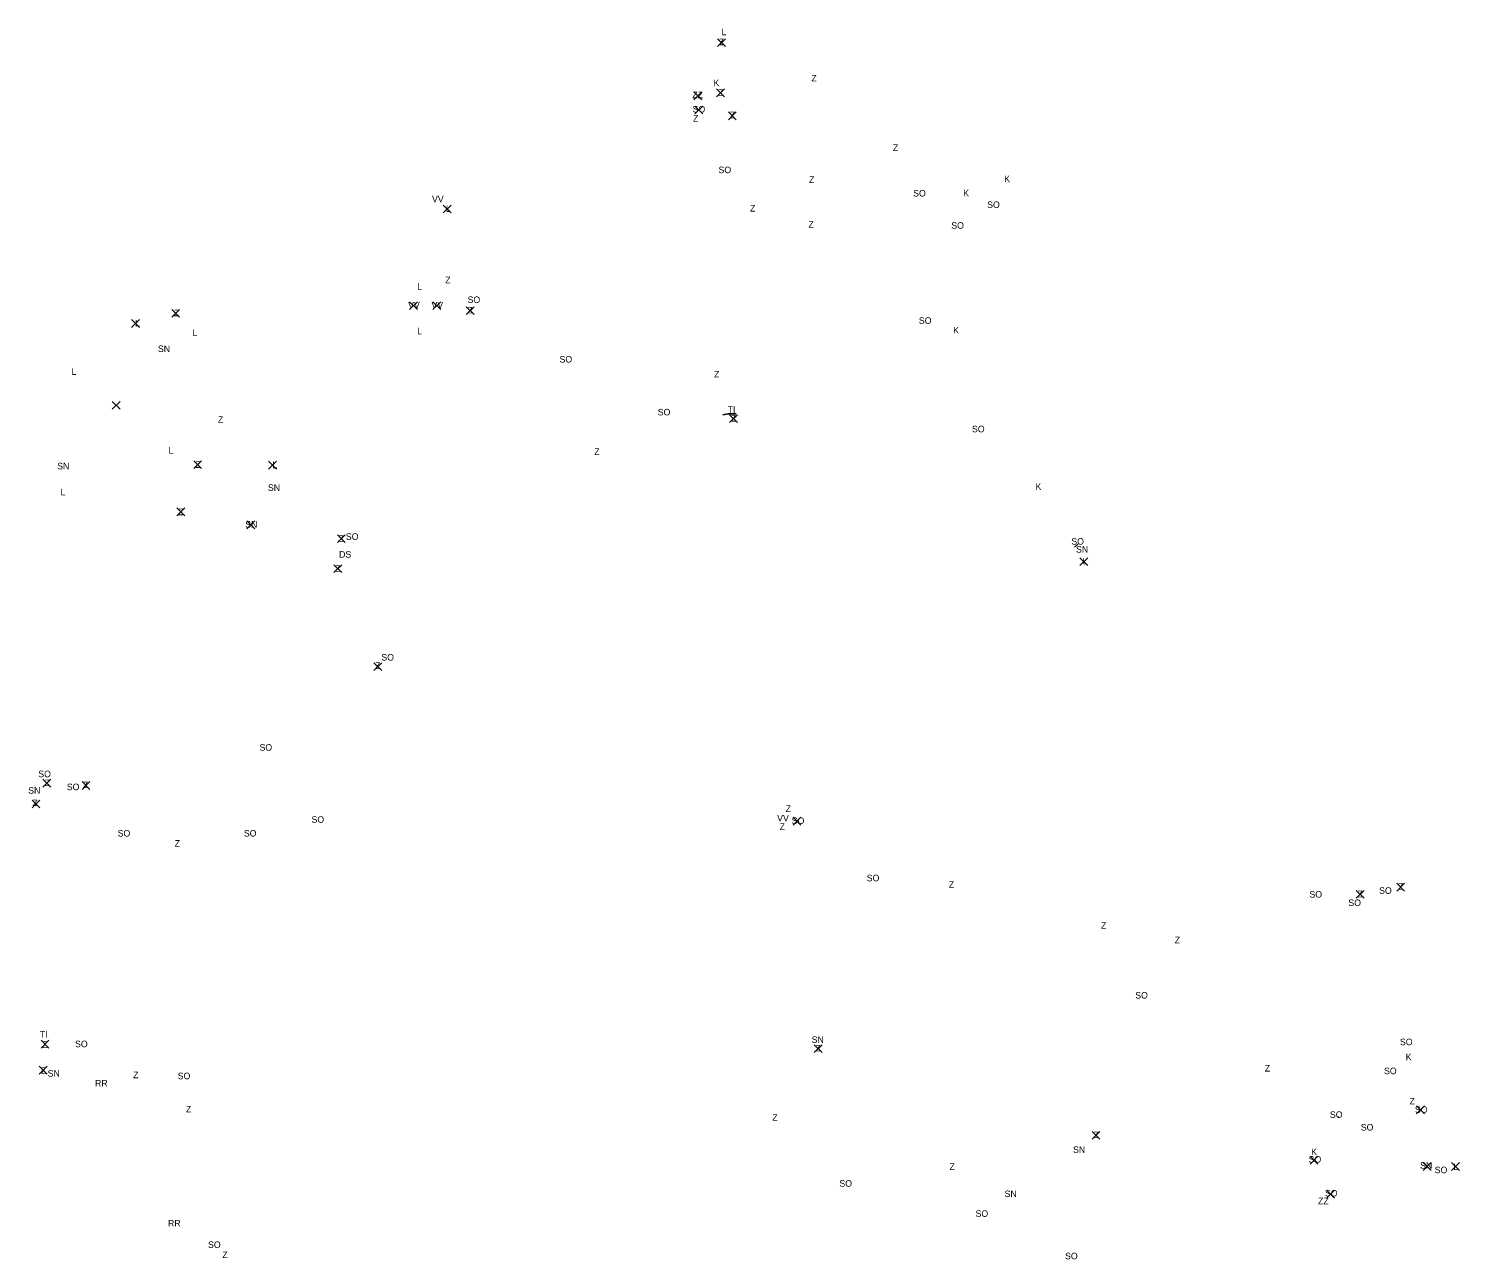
# Model space of a CAD drawing. Extents: x -444381 to -436234, y -1141793 to -1129925.
# Drawn here: x -442927 to -440739, y -1131807 to -1129925 of the extents above; entities that cross this region are included whole.
import ezdxf

# ---------------------------------------------------------------- set-up
doc = ezdxf.new("R2010")
doc.units = 0
for name, color, linetype in [('Implicitní', 7, 'Continuous'), ('Vrstva 200', 7, 'Continuous'), ('Vrstva 4', 7, 'Continuous')]:
    doc.layers.add(name, color=color, linetype=linetype)

msp = doc.modelspace()

# ---------------------------------------------------------------- linework, layer by layer
at = {"layer": 'Implicitní'}
msp.add_line((-440923.8, -1131589), (-440923.6, -1131589.3), dxfattribs=at)
at = {"layer": 'Vrstva 200'}
for p, q in [((-441873.3, -1129952.3), (-441861.3, -1129940.3)), ((-441873.3, -1129940.3), (-441861.3, -1129952.3)), ((-441909.4, -1130033.7), (-441897.4, -1130021.7)), ((-441909.4, -1130021.7), (-441897.4, -1130033.7)), ((-441874.8, -1130029), (-441862.8, -1130017)), ((-441874.8, -1130017), (-441862.8, -1130029)), ((-441908, -1130055.3), (-441896, -1130043.3)), ((-441908, -1130043.3), (-441896, -1130055.3)), ((-441856.7, -1130064.2), (-441844.7, -1130052.2)), ((-441856.7, -1130052.2), (-441844.7, -1130064.2)), ((-442292.6, -1130206.8), (-442280.6, -1130194.8)), ((-442292.6, -1130194.8), (-442280.6, -1130206.8)), ((-442344.1, -1130354.6), (-442332.1, -1130342.6)), ((-442344.1, -1130342.6), (-442332.1, -1130354.6)), ((-442308.3, -1130354.6), (-442296.3, -1130342.6)), ((-442308.3, -1130342.6), (-442296.3, -1130354.6)), ((-442257.5, -1130362.3), (-442245.5, -1130350.3)), ((-442257.5, -1130350.3), (-442245.5, -1130362.3)), ((-442769.1, -1130381.9), (-442757.1, -1130369.9)), ((-442769.1, -1130369.9), (-442757.1, -1130381.9)), ((-442707.8, -1130366.2), (-442695.8, -1130354.2)), ((-442707.8, -1130354.2), (-442695.8, -1130366.2)), ((-442798.6, -1130507), (-442786.6, -1130495)), ((-442798.6, -1130495), (-442786.6, -1130507)), ((-441854.8, -1130527.4), (-441842.8, -1130515.4)), ((-441854.8, -1130515.4), (-441842.8, -1130527.4)), ((-442674, -1130597.6), (-442662, -1130585.6)), ((-442674, -1130585.6), (-442662, -1130597.6)), ((-442559.6, -1130598.6), (-442547.6, -1130586.6)), ((-442559.6, -1130586.6), (-442547.6, -1130598.6)), ((-442699.9, -1130669.9), (-442687.9, -1130657.9)), ((-442699.9, -1130657.9), (-442687.9, -1130669.9)), ((-442592.8, -1130689.7), (-442580.8, -1130677.7)), ((-442592.8, -1130677.7), (-442580.8, -1130689.7)), ((-442454.4, -1130710.9), (-442442.4, -1130698.9)), ((-442454.4, -1130698.9), (-442442.4, -1130710.9)), ((-442459.7, -1130756.8), (-442447.7, -1130744.8)), ((-442459.7, -1130744.8), (-442447.7, -1130756.8)), ((-441319.3, -1130746.1), (-441307.3, -1130734.1)), ((-441319.3, -1130734.1), (-441307.3, -1130746.1)), ((-442398.5, -1130906.6), (-442386.5, -1130894.6)), ((-442398.5, -1130894.6), (-442386.5, -1130906.6)), ((-442904.8, -1131084.9), (-442892.8, -1131072.9)), ((-442904.8, -1131072.9), (-442892.8, -1131084.9)), ((-442844.8, -1131088.3), (-442832.8, -1131076.3)), ((-442844.8, -1131076.3), (-442832.8, -1131088.3)), ((-442921.2, -1131116.6), (-442909.2, -1131104.6)), ((-442921.2, -1131104.6), (-442909.2, -1131116.6)), ((-441757.7, -1131142.9), (-441745.7, -1131130.9)), ((-441757.7, -1131130.9), (-441745.7, -1131142.9)), ((-440896.8, -1131254.9), (-440884.8, -1131242.9)), ((-440896.8, -1131242.9), (-440884.8, -1131254.9)), ((-440834.8, -1131243.9), (-440822.8, -1131231.9)), ((-440834.8, -1131231.9), (-440822.8, -1131243.9)), ((-442907.4, -1131483.9), (-442895.4, -1131471.9)), ((-442907.4, -1131471.9), (-442895.4, -1131483.9)), ((-441725.5, -1131490.9), (-441713.5, -1131478.9)), ((-441725.5, -1131478.9), (-441713.5, -1131490.9)), ((-442910.4, -1131523.6), (-442898.4, -1131511.6)), ((-442910.4, -1131511.6), (-442898.4, -1131523.6)), ((-440804.7, -1131584.4), (-440792.7, -1131572.4)), ((-440804.7, -1131572.4), (-440792.7, -1131584.4)), ((-441300.7, -1131623.3), (-441288.7, -1131611.3)), ((-441300.7, -1131611.3), (-441288.7, -1131623.3)), ((-440967.4, -1131661.3), (-440955.4, -1131649.3)), ((-440967.4, -1131649.3), (-440955.4, -1131661.3)), ((-440794.5, -1131671), (-440782.5, -1131659)), ((-440794.5, -1131659), (-440782.5, -1131671)), ((-440751.1, -1131671), (-440739.1, -1131659)), ((-440751.1, -1131659), (-440739.1, -1131671)), ((-440942.1, -1131713.2), (-440930.1, -1131701.2)), ((-440942.1, -1131701.2), (-440930.1, -1131713.2))]:
    msp.add_line(p, q, dxfattribs=at)
at = {"layer": 'Vrstva 4'}
msp.add_line((-441322.7, -1130713.5), (-441327.7, -1130717.9), dxfattribs=at)
msp.add_lwpolyline([(-441844.6, -1130513.9), (-441856.9, -1130513.9), (-441865.4, -1130515.5)], dxfattribs=at)

# ---------------------------------------------------------------- texts
for s, p in [('L', (-441867.2, -1129934.9)), ('Z', (-441871.6, -1129950.2)), ('K', (-441879.5, -1130012.9)), ('Z', (-441729.9, -1130005.7)), ('ZZ', (-441911.9, -1130031.3)), ('Z', (-441872.5, -1130027.5)), ('SO', (-441911.4, -1130053.1)), ('Z', (-441910.8, -1130067.1)), ('Z', (-441854.7, -1130062)), ('Z', (-441605.2, -1130112)), ('SO', (-441871.8, -1130145.9)), ('Z', (-441733.5, -1130160.9)), ('K', (-441435, -1130159.7)), ('SO', (-441574.2, -1130181.6)), ('K', (-441497.7, -1130181.4)), ('VV', (-442309.8, -1130190.5)), ('L', (-442288.6, -1130205.1)), ('Z', (-441823.6, -1130204.6)), ('SO', (-441461.1, -1130199.2)), ('Z', (-441734.4, -1130229.4)), ('SO', (-441515.9, -1130230.9)), ('Z', (-442289.6, -1130314.3)), ('L', (-442332.4, -1130324.1)), ('VV', (-442346.3, -1130352.7)), ('VV', (-442310.6, -1130352.7)), ('Z', (-442255.6, -1130360.4)), ('SO', (-442255.4, -1130344.5)), ('L', (-442763.7, -1130380.3)), ('Z', (-442704.6, -1130364.7)), ('SO', (-441565.5, -1130376.3)), ('L', (-442676, -1130395)), ('L', (-442332.4, -1130392.3)), ('K', (-441513, -1130391.1)), ('SN', (-442728.8, -1130419.5)), ('SO', (-442114.8, -1130435.6)), ('L', (-442861, -1130454.4)), ('Z', (-441878.6, -1130458.4)), ('SO', (-441964.7, -1130516.4)), ('TI', (-441857.8, -1130512.6)), ('Z', (-442637.1, -1130527.6)), ('Z', (-441853.1, -1130525.7)), ('SO', (-441484.3, -1130542.2)), ('L', (-442712.6, -1130574.9)), ('Z', (-442061.7, -1130576.8)), ('SN', (-442882.8, -1130598.9)), ('Z', (-442671.7, -1130596.6)), ('L', (-442553.9, -1130597.1)), ('L', (-442877.6, -1130638.5)), ('SN', (-442560.7, -1130631.9)), ('K', (-441387.1, -1130630.2)), ('Z', (-442697.6, -1130669)), ('SN', (-442595.3, -1130688.1)), ('Z', (-442452.8, -1130709.7)), ('SO', (-442441.5, -1130706.7)), ('SO', (-441332.4, -1130714)), ('DS', (-442451.9, -1130733.9)), ('SN', (-441325.2, -1130726.2)), ('Z', (-442458.1, -1130755.5)), ('L', (-441315.3, -1130744.3)), ('Z', (-442396.9, -1130904.1)), ('SO', (-442387.3, -1130891.3)), ('SO', (-442573.5, -1131029.1)), ('SO', (-442911.8, -1131069.7)), ('Z', (-442902, -1131083.3)), ('SN', (-442927.1, -1131094.9)), ('SO', (-442868.1, -1131089.5)), ('Z', (-442843.6, -1131086.4)), ('Z', (-442920.6, -1131113.9)), ('Z', (-441769.2, -1131122.8)), ('SO', (-442494, -1131139.4)), ('VV', (-441782.1, -1131137.3)), ('Z', (-441778.4, -1131150.3)), ('SO', (-441759.9, -1131141.1)), ('SO', (-442790.4, -1131160.4)), ('SO', (-442597.5, -1131160.4)), ('Z', (-442703.2, -1131175.9)), ('SO', (-441645.2, -1131228.8)), ('Z', (-441519.7, -1131238.7)), ('SO', (-440968.4, -1131253.8)), ('Z', (-440895.1, -1131253.3)), ('SO', (-440861.9, -1131248)), ('Z', (-440832.8, -1131241.9)), ('SO', (-440908.9, -1131266.7)), ('Z', (-441287, -1131301.4)), ('Z', (-441174.3, -1131323.6)), ('SO', (-441234.7, -1131408.1)), ('TI', (-442909.5, -1131467.8)), ('SN', (-441729.3, -1131476.1)), ('SO', (-440830, -1131479.5)), ('Z', (-442905.7, -1131483.7)), ('SO', (-442855.5, -1131482.6)), ('Z', (-441723.8, -1131489)), ('Z', (-442907.4, -1131523.1)), ('Z', (-441036.6, -1131519.8)), ('K', (-440821.2, -1131502.5)), ('SN', (-442897.4, -1131527.6)), ('RR', (-442825, -1131542.6)), ('Z', (-442766.7, -1131530)), ('SO', (-442698.6, -1131531.5)), ('SO', (-440854.4, -1131523.8)), ('Z', (-442686, -1131582.3)), ('Z', (-440815.3, -1131570.1)), ('SO', (-440807.1, -1131583)), ('Z', (-441789.6, -1131595.1)), ('SO', (-440937.1, -1131590.7)), ('SO', (-440889.9, -1131610)), ('Z', (-441298.5, -1131621.5)), ('SN', (-441329.8, -1131644.2)), ('K', (-440965.7, -1131647.5)), ('Z', (-441518.6, -1131670.2)), ('SO', (-440969.6, -1131659)), ('SN', (-440799.2, -1131668.4)), ('SO', (-440776.9, -1131675.3)), ('L', (-440748.3, -1131670.6)), ('SO', (-441687, -1131695.9)), ('SN', (-441434.4, -1131711.8)), ('SO', (-440944.7, -1131710.8)), ('SO', (-441478.8, -1131742)), ('ZZ', (-440955.2, -1131722.7)), ('RR', (-442713.4, -1131756.6)), ('SO', (-442652.2, -1131789.6)), ('Z', (-442630.4, -1131805)), ('SO', (-441342, -1131806.9))]:
    msp.add_text(s, height=10, dxfattribs=at).set_placement(p)

doc.saveas('drawing.dxf')
